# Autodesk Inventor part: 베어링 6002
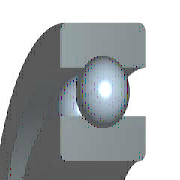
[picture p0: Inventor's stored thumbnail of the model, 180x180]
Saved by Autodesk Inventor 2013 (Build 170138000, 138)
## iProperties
IsCustomPart: 0
Created: 2012-02
Part Number: 베어링 6002
Material: 강철, 연강
Description: 깊은 그루브 볼 베어링
Document SubType Name: Modeling
Standard: KS B 2023
Designer: mduedu
Standards Organization: KS
Language: ko-KR
Size Designation: 6002 - 15 x 32 x 9
Categories: <MemberInstance><Categories><Category DisplayName="샤프트 부품" InternalName="7f7aeb1f-a693-4053-b835-cee3144e0d98" Mnemonic="SHFT"><Category DisplayName="베어링" Inter
Density: 7.86 g/cm^3
Mass: 29.8124 g
Surface Area: 39.9079 cm^2
Volume: 3.79293 cm^3
Author: mduedu
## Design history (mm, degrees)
sketch "스케치" dims "d0" = 4.42 (= -0.26 x WD + 0.26 x BD)
  geometry: L1 (2.29, 11.75)-(6.71, 11.75); L2 (4.5, 11.75)-(4.5, 9.54); L3 (4.5, 11.75)-(4.5, 13.96); L4 (2.858, 10.271)-(0, 10.271); L5 (0, 7.5)-(9, 7.5); L6 (2.858, 13.229)-(0, 13.229); L7 (0, 16)-(9, 16); L8 (9, 7.5)-(9, 10.271); L9 (6.142, 10.271)-(9, 10.271); L10 (6.142, 13.229)-(9, 13.229); L11 (9, 16)-(9, 13.229); L12 (-1.4, 0)-(8.4, 0) reference; L13 (0, -0.3)-(0, 5.3) reference
  constraints: 22 end point, 4 point on line, 2 collinear, 2 perpendicular, 2 symmetric about line, 1 midpoint, 1 parallel, 14 other
  dimensions: "d9" = 15 diameter of L5 L12 (= WD); "d11" = 32 diameter of L7 L12 (= BD); "d12" = 9 distance between parallel lines of L8 L13 (= KB); "d13" = 20.542 diameter of L9 L12 (= 0.326 x BD + 0.674 x WD)
revolve "본체" stored, may be unused: angle "d6" = 90 deg
revolve "볼" stored, may be unused: angle "d7" = 90 deg
pattern_circular "IDS_ARRAYBALL[SIMPL:T]" dims angle "d3" = 360 deg
body "Solid1"
fillet "모깎기1" dims "d1" = 0.3 (= KRS)
other parameters: "WD" = 15 [user parameter; used in 5 equation terms], "BD" = 32 [user parameter; used in 5 equation terms], "KB" = 9 [user parameter; used in 1 equation term], "KRS" = 0.3 [user parameter; used in 1 equation term], "d4" = 0, "d5" = 0, "d8" = 0, "d14" = 0, "d15" = 0, "BBA" = 0 [user parameter], "BC0" = 2850000 [user parameter], "BC" = 5590000 [user parameter], "BR" = 16 (= 0.5 x BD) [user parameter], "WR" = 7.5 (= 0.5 x WD) [user parameter]
